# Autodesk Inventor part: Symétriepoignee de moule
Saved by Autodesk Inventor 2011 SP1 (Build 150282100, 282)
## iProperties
Created: 2010-12
Part Number: Symétriepoignee de moule
Document SubType Name: Modeling
Designer: eric
Density: 1 g/cm^3
Author: eric
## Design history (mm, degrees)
feature "Base1"
node "Solide1"
node "Corps solides"
node "Corps surfaciques"
